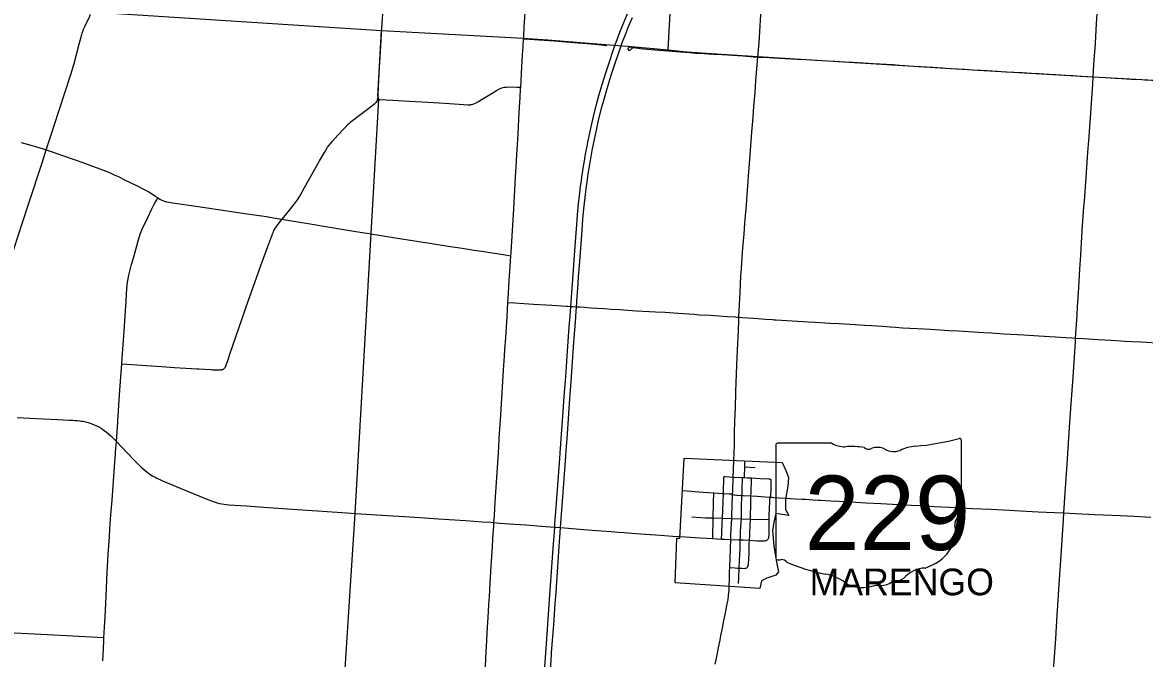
# Model space of a CAD drawing. Extents: x 1815539 to 1947826, y 273303 to 993194.
# Drawn here: x 1868609 to 1889640, y 872057 to 883973 of the extents above; entities that cross this region are included whole.
import ezdxf

# ---------------------------------------------------------------- set-up
doc = ezdxf.new("R2010")
doc.units = 0
for name, color, linetype in [('GM_X_City_Street', 7, 'Continuous'), ('GM_X_Corporation', 7, 'Continuous'), ('GM_X_Corporation_Text', 7, 'Continuous'), ('GM_X_County_Road', 7, 'Continuous'), ('GM_X_Interstate_Route', 7, 'Continuous'), ('GM_X_State_Route', 7, 'Continuous'), ('GM_X_Township', 7, 'Continuous'), ('GM_X_Township_Road', 7, 'Continuous'), ('SC_Shading3', 7, 'Continuous')]:
    doc.layers.add(name, color=color, linetype=linetype)

msp = doc.modelspace()

# ---------------------------------------------------------------- linework, layer by layer
at = {"layer": 'GM_X_City_Street'}
for points in [[(1881932, 875457), (1881937, 875598), (1881944, 875773)], [(1882141, 875447), (1882142, 875472), (1882148, 875648)], [(1882148, 875648), (1882150, 875743)], [(1882148, 875648), (1882345, 875639)], [(1881746, 875151), (1881748, 875210), (1881753, 875413), (1881754, 875448), (1881755, 875454), (1881756, 875459)], [(1881756, 875459), (1881758, 875463), (1881761, 875464), (1881763, 875465), (1881769, 875466), (1881779, 875465), (1881860, 875461), (1881932, 875457)], [(1881919, 875132), (1881922, 875192), (1881932, 875457)], [(1881932, 875457), (1882107, 875449)], [(1882094, 875113), (1882096, 875155), (1882098, 875223), (1882107, 875449)], [(1882107, 875449), (1882141, 875447)], [(1882141, 875447), (1882192, 875445), (1882275, 875440)], [(1882263, 875103), (1882265, 875158), (1882275, 875432), (1882275, 875440)], [(1882275, 875440), (1882437, 875431), (1882599, 875422), (1882610, 875421), (1882619, 875420), (1882625, 875418), (1882630, 875415), (1882634, 875412)], [(1882626, 875081), (1882633, 875113), (1882635, 875129), (1882639, 875210), (1882643, 875341), (1882643, 875363), (1882641, 875387), (1882639, 875401), (1882637, 875407), (1882634, 875412)], [(1880983, 875205), (1881064, 875200), (1881147, 875193), (1881212, 875188), (1881288, 875183), (1881370, 875176), (1881566, 875163)], [(1881557, 874690), (1881560, 874969), (1881566, 875163)], [(1881566, 875163), (1881728, 875152), (1881746, 875151)], [(1881729, 874686), (1881734, 874837), (1881746, 875151)], [(1881746, 875151), (1881854, 875143), (1881884, 875141), (1881899, 875140), (1881914, 875136), (1881919, 875132)], [(1882084, 874674), (1882085, 874772), (1882089, 874927), (1882093, 875074), (1882094, 875113)], [(1882252, 874668), (1882255, 874793), (1882259, 874868), (1882261, 874951), (1882262, 875016), (1882263, 875097), (1882263, 875103)], [(1882606, 874659), (1882607, 874738), (1882615, 875000), (1882618, 875050), (1882621, 875066), (1882626, 875081)], [(1881153, 874710), (1881236, 874706), (1881417, 874696), (1881557, 874690)], [(1881548, 874306), (1881557, 874690)], [(1881557, 874690), (1881729, 874686)], [(1881712, 874296), (1881717, 874404), (1881723, 874587), (1881729, 874686)], [(1881729, 874686), (1881902, 874681)], [(1881902, 874681), (1882084, 874674)], [(1882063, 874280), (1882065, 874335), (1882068, 874388), (1882069, 874430), (1882075, 874528), (1882084, 874674)], [(1882084, 874674), (1882252, 874668)], [(1882233, 874273), (1882237, 874298), (1882239, 874323), (1882240, 874345), (1882244, 874418), (1882249, 874545), (1882252, 874658), (1882252, 874668)], [(1882252, 874668), (1882606, 874659)], [(1882571, 874282), (1882582, 874294), (1882590, 874307), (1882596, 874321), (1882599, 874337), (1882602, 874368), (1882605, 874577), (1882606, 874659)], [(1881866, 873762), (1881884, 874288)], [(1881884, 874288), (1882039, 874281), (1882063, 874280)], [(1882043, 873751), (1882048, 873890), (1882053, 874009), (1882058, 874124), (1882062, 874259), (1882063, 874280)], [(1882063, 874280), (1882121, 874278), (1882233, 874273)], [(1882233, 874273), (1882235, 874272), (1882377, 874265), (1882453, 874263), (1882485, 874262), (1882517, 874264), (1882533, 874266), (1882549, 874271), (1882571, 874282)], [(1882186, 873759), (1882198, 873770), (1882206, 873781), (1882212, 873800), (1882216, 873816), (1882220, 873849), (1882222, 873898), (1882227, 874054), (1882229, 874164), (1882230, 874211), (1882233, 874263), (1882233, 874273)], [(1881855, 873411), (1881859, 873535), (1881863, 873690), (1881866, 873762)], [(1881866, 873762), (1881873, 873762), (1881959, 873756), (1882007, 873753), (1882043, 873751)], [(1882031, 873462), (1882034, 873561), (1882043, 873751)], [(1882043, 873751), (1882092, 873748), (1882137, 873747), (1882153, 873748), (1882170, 873753), (1882186, 873759)]]:
    msp.add_lwpolyline(points, dxfattribs=at)
at = {"layer": 'GM_X_Corporation'}
msp.add_lwpolyline([(1881014, 875812), (1882849, 875731), (1882917, 875580), (1882968, 875451), (1882954, 875285), (1882910, 875039), (1882912, 874849), (1882974, 874736), (1882727, 874773), (1882689, 874613), (1882670, 874451), (1882695, 874167), (1882739, 873862), (1882781, 873681), (1882728, 873621), (1882559, 873563), (1882458, 873515), (1882428, 873371), (1880842, 873478), (1880871, 874310), (1880929, 874307)], close=True, dxfattribs=at)
at = {"layer": 'GM_X_County_Road'}
for points in [[(1875340, 883767), (1875347, 883875), (1875368, 884219), (1875408, 884824), (1875439, 885315), (1875466, 885691), (1875483, 885919), (1875493, 886066), (1875504, 886222), (1875516, 886361), (1875526, 886521)], [(1882394, 883327), (1882396, 883347), (1882399, 883397), (1882414, 883594), (1882429, 883806), (1882450, 884118), (1882466, 884380), (1882480, 884592), (1882489, 884773), (1882494, 884904), (1882502, 885051), (1882505, 885117), (1882513, 885297), (1882517, 885379), (1882523, 885510), (1882528, 885641), (1882535, 885805), (1882538, 885887), (1882542, 885985), (1882549, 886108)], [(1888677, 882955), (1888685, 883069), (1888692, 883183), (1888703, 883347), (1888718, 883576), (1888726, 883707), (1888734, 883838), (1888745, 884050), (1888750, 884132), (1888766, 884378), (1888781, 884607), (1888793, 884803), (1888810, 885032), (1888820, 885196), (1888836, 885408), (1888848, 885605), (1888852, 885654)], [(1869055, 881586), (1869128, 881814), (1869298, 882328), (1869410, 882671), (1869517, 882998), (1869576, 883203), (1869673, 883568), (1869707, 883702), (1869716, 883732), (1869720, 883746), (1869727, 883770), (1869734, 883791), (1869744, 883819), (1869756, 883848), (1869765, 883870), (1869778, 883895), (1869843, 884028), (1869863, 884071), (1869881, 884118), (1869883, 884123)], [(1875266, 882530), (1875266, 882534), (1875270, 882552), (1875273, 882582), (1875284, 882778), (1875304, 883138), (1875332, 883629), (1875340, 883767)], [(1882038, 878451), (1882059, 878916), (1882067, 879063), (1882075, 879227), (1882079, 879292), (1882092, 879456), (1882100, 879570), (1882113, 879750), (1882133, 880012), (1882147, 880208), (1882159, 880355), (1882177, 880550), (1882193, 880747), (1882211, 880992), (1882219, 881106), (1882242, 881401), (1882275, 881842), (1882302, 882202), (1882319, 882398), (1882339, 882659), (1882357, 882888), (1882375, 883100), (1882394, 883327)], [(1888348, 878062), (1888353, 878138), (1888376, 878498), (1888385, 878646), (1888407, 879006), (1888429, 879349), (1888446, 879611), (1888466, 879955), (1888479, 880167), (1888504, 880511), (1888512, 880625), (1888551, 881165), (1888578, 881541), (1888593, 881754), (1888619, 882097), (1888670, 882817), (1888677, 882955)], [(1873476, 880289), (1873563, 880397), (1873708, 880574), (1873766, 880653), (1873810, 880722), (1873897, 880880), (1874034, 881123), (1874179, 881380), (1874268, 881537), (1874293, 881579), (1874329, 881637), (1874358, 881675), (1874420, 881751), (1874520, 881860), (1874642, 881992), (1874723, 882074), (1874772, 882118), (1874795, 882136), (1874902, 882219), (1875099, 882366), (1875189, 882435), (1875213, 882453), (1875226, 882465), (1875239, 882478), (1875244, 882483), (1875248, 882489), (1875253, 882497), (1875256, 882503), (1875261, 882512), (1875264, 882521), (1875266, 882530)], [(1866649, 876676), (1866673, 876713), (1866803, 876919), (1867040, 877293), (1867199, 877542), (1867365, 877805), (1867523, 878055), (1867681, 878305), (1867786, 878471), (1867936, 878706), (1868077, 878927), (1868253, 879204), (1868289, 879272), (1868302, 879298), (1868309, 879316), (1868322, 879354), (1868390, 879553), (1868526, 879975), (1868609, 880223), (1868720, 880567), (1868977, 881346), (1869055, 881586)], [(1871921, 877483), (1872131, 877470), (1872174, 877468), (1872233, 877465), (1872280, 877463), (1872303, 877463), (1872317, 877465), (1872335, 877467), (1872349, 877470), (1872357, 877473), (1872363, 877475), (1872375, 877480), (1872384, 877485), (1872391, 877491), (1872397, 877496), (1872402, 877501), (1872407, 877507), (1872411, 877513), (1872416, 877522), (1872420, 877529), (1872423, 877538), (1872454, 877624), (1872504, 877780), (1872664, 878246), (1872847, 878772), (1872995, 879190), (1873079, 879421), (1873208, 879775), (1873280, 879976), (1873299, 880025), (1873312, 880052), (1873322, 880073), (1873335, 880096), (1873346, 880114), (1873371, 880151), (1873460, 880269), (1873476, 880289)], [(1881944, 875773), (1881952, 876049), (1881957, 876279), (1881964, 876508), (1881971, 876754), (1881981, 877049), (1881987, 877229), (1881993, 877376), (1881999, 877557), (1882012, 877835), (1882028, 878195), (1882036, 878408), (1882038, 878451)], [(1888128, 874784), (1888154, 875161), (1888190, 875701), (1888216, 876094), (1888235, 876388), (1888258, 876748), (1888294, 877238), (1888331, 877795), (1888344, 877991), (1888348, 878062)], [(1870394, 876484), (1870396, 876514), (1870437, 877087), (1870460, 877414), (1870472, 877577)], [(1870472, 877577), (1871214, 877526), (1871460, 877510), (1871886, 877485), (1871921, 877483)], [(1870371, 876121), (1870394, 876484)], [(1870356, 875926), (1870371, 876121)], [(1870137, 872450), (1870143, 872537), (1870149, 872651), (1870154, 872733), (1870164, 872962), (1870176, 873224), (1870197, 873667), (1870218, 874011), (1870238, 874338), (1870248, 874486), (1870268, 874747), (1870291, 875025), (1870337, 875647), (1870354, 875892), (1870356, 875926)], [(1887918, 871548), (1887924, 871662), (1887953, 872087), (1887976, 872429), (1887990, 872658), (1888004, 872870), (1888017, 873050), (1888042, 873443), (1888071, 873901), (1888119, 874654), (1888128, 874784)], [(1881591, 871952), (1881615, 872067), (1881668, 872319), (1881683, 872399), (1881701, 872487), (1881717, 872568), (1881734, 872660), (1881750, 872737), (1881780, 872881), (1881800, 872979), (1881819, 873079), (1881833, 873160), (1881843, 873242), (1881852, 873340), (1881855, 873411)], [(1870115, 872014), (1870126, 872244), (1870134, 872391), (1870137, 872450)]]:
    msp.add_lwpolyline(points, dxfattribs=at)
at = {"layer": 'GM_X_Interstate_Route'}
for points in [[(1878372, 871564), (1878428, 872333), (1878482, 873069), (1878552, 874035), (1878585, 874519), (1878590, 874591), (1878613, 874886), (1878650, 875393), (1878674, 875720), (1878695, 875998), (1878743, 876686), (1878764, 876964), (1878785, 877258), (1878803, 877520), (1878812, 877635), (1878825, 877815), (1878858, 878273), (1878872, 878469), (1878886, 878654), (1878892, 878731), (1878899, 878829), (1878923, 879156), (1878956, 879615), (1878979, 879942), (1878997, 880187), (1879012, 880367), (1879024, 880498), (1879032, 880579), (1879048, 880726), (1879062, 880840), (1879071, 880905), (1879084, 881002), (1879096, 881083), (1879106, 881148), (1879121, 881246), (1879137, 881343), (1879151, 881423), (1879165, 881504), (1879183, 881601), (1879198, 881682), (1879207, 881730), (1879230, 881842), (1879268, 882019), (1879313, 882210), (1879365, 882417), (1879421, 882623), (1879476, 882812), (1879543, 883031), (1879604, 883218), (1879688, 883467), (1879708, 883521), (1879755, 883652), (1879808, 883790), (1879882, 883972), (1879977, 884199)], [(1879025, 879077), (1879033, 879208), (1879048, 879421), (1879074, 879748), (1879098, 880075), (1879114, 880288), (1879132, 880484), (1879154, 880696), (1879174, 880859), (1879192, 880989), (1879213, 881135), (1879242, 881314), (1879287, 881572), (1879328, 881782), (1879366, 881958), (1879414, 882166), (1879470, 882389), (1879522, 882579), (1879585, 882799), (1879643, 882988), (1879709, 883191), (1879784, 883408), (1879823, 883517), (1879845, 883578), (1879909, 883746), (1879971, 883899), (1880040, 884065)], [(1878974, 878366), (1878980, 878456), (1878989, 878571), (1878993, 878636), (1878994, 878648), (1878995, 878653), (1879000, 878718), (1879002, 878750), (1879020, 878996), (1879025, 879077)], [(1878830, 876359), (1878863, 876837), (1878881, 877082), (1878893, 877246), (1878907, 877426), (1878914, 877524), (1878946, 877982), (1878974, 878366)], [(1878793, 875843), (1878801, 875953), (1878818, 876182), (1878830, 876359)], [(1878598, 873152), (1878604, 873221), (1878610, 873303), (1878643, 873777), (1878677, 874252), (1878689, 874415), (1878696, 874510), (1878738, 875086), (1878768, 875511), (1878793, 875843)], [(1878526, 872162), (1878566, 872697), (1878593, 873090), (1878598, 873152)], [(1878393, 870309), (1878407, 870521), (1878419, 870685), (1878440, 870963), (1878463, 871290), (1878503, 871830), (1878525, 872141), (1878526, 872162)]]:
    msp.add_lwpolyline(points, dxfattribs=at)
at = {"layer": 'GM_X_State_Route'}
for points in [[(1877447, 874606), (1877455, 874740), (1877471, 874986), (1877494, 875362), (1877518, 875722), (1877537, 876017), (1877547, 876181), (1877573, 876623), (1877594, 876933), (1877615, 877244), (1877628, 877457), (1877644, 877719), (1877652, 877850), (1877666, 878063), (1877691, 878456), (1877708, 878729), (1877719, 878897), (1877733, 879143), (1877743, 879307), (1877756, 879503), (1877763, 879600), (1877767, 879667), (1877786, 879978), (1877810, 880371), (1877837, 880829), (1877851, 881075), (1877861, 881271), (1877875, 881500), (1877892, 881779), (1877905, 882008), (1877914, 882172), (1877926, 882384), (1877936, 882565), (1877946, 882728), (1877948, 882762), (1877955, 882875), (1877963, 883023), (1877969, 883137), (1877983, 883366), (1877991, 883514), (1878002, 883665), (1878004, 883711), (1878014, 883891), (1878029, 884153)], [(1868509, 876574), (1868869, 876554), (1869263, 876537), (1869379, 876530), (1869479, 876525)], [(1869479, 876525), (1869494, 876524), (1869554, 876521), (1869592, 876518), (1869632, 876515), (1869677, 876510), (1869710, 876506), (1869740, 876501), (1869774, 876495), (1869814, 876486), (1869841, 876479), (1869876, 876468), (1869909, 876455), (1869952, 876438), (1869985, 876424), (1870026, 876403), (1870082, 876371), (1870138, 876332), (1870183, 876298), (1870223, 876264), (1870270, 876221), (1870344, 876149), (1870371, 876121), (1870695, 875781), (1870834, 875642), (1870908, 875577), (1870947, 875546), (1870974, 875527), (1871014, 875500), (1871043, 875483), (1871094, 875454), (1871130, 875435), (1871207, 875399)], [(1871207, 875399), (1871234, 875386), (1871567, 875248), (1871916, 875103), (1872113, 875023), (1872222, 874985), (1872258, 874974), (1872301, 874963), (1872346, 874954), (1872425, 874943), (1872480, 874936), (1872808, 874915), (1873135, 874891), (1873577, 874861), (1873953, 874837), (1874510, 874799), (1874769, 874782), (1874952, 874770), (1875443, 874739), (1875770, 874715), (1876146, 874690), (1876408, 874673), (1876916, 874641), (1877227, 874619), (1877391, 874609), (1877447, 874606)], [(1881889, 874394), (1881902, 874681), (1881904, 874741), (1881910, 874906), (1881919, 875132)], [(1881919, 875132), (1881941, 875125), (1881950, 875122), (1881962, 875121), (1881999, 875119), (1882094, 875113), (1882118, 875111), (1882263, 875103), (1882380, 875096), (1882531, 875088), (1882626, 875081), (1882661, 875080), (1882694, 875077)], [(1882694, 875077), (1882795, 875070), (1882918, 875062)], [(1882918, 875062), (1883090, 875051), (1883219, 875044)], [(1883219, 875044), (1883285, 875040), (1883420, 875031), (1883530, 875026)], [(1883530, 875026), (1883559, 875024), (1883761, 875013), (1883908, 875005), (1884138, 874993), (1884416, 874977), (1884695, 874960), (1885137, 874936), (1885268, 874930), (1885448, 874921), (1885694, 874908), (1885989, 874893), (1886202, 874883), (1886415, 874871), (1886759, 874853), (1887103, 874835), (1887316, 874825), (1887644, 874807), (1887955, 874792), (1888128, 874784), (1888349, 874773), (1888709, 874757), (1889184, 874737), (1889446, 874722), (1889758, 874704)], [(1877285, 871892), (1877296, 872072), (1877308, 872285), (1877328, 872645), (1877338, 872825), (1877351, 873071), (1877361, 873218), (1877376, 873464), (1877394, 873791), (1877404, 873971), (1877416, 874151), (1877425, 874299), (1877443, 874544), (1877447, 874606)], [(1877447, 874606), (1877555, 874595), (1877735, 874583), (1878044, 874559), (1878338, 874538), (1878583, 874519), (1878585, 874519), (1878696, 874510), (1878844, 874499), (1879056, 874482), (1879284, 874465), (1879464, 874451), (1879643, 874437), (1879782, 874426)], [(1879782, 874426), (1879888, 874418), (1880100, 874402), (1880566, 874369)], [(1880566, 874369), (1880876, 874346), (1880935, 874342)], [(1880935, 874342), (1881310, 874320), (1881548, 874306), (1881712, 874296), (1881766, 874293), (1881884, 874288), (1881884, 874291), (1881889, 874394)]]:
    msp.add_lwpolyline(points, dxfattribs=at)
at = {"layer": 'GM_X_Township'}
for points in [[(1880714, 883463), (1880836, 885744), (1880863, 886256), (1881338, 891636), (1881703, 897023), (1881803, 900282), (1881806, 900375), (1881918, 903829), (1881985, 905459), (1882074, 908232), (1882082, 908847), (1882260, 912507), (1887758, 913255), (1888309, 913332)], [(1850147, 879854), (1850364, 882693), (1850523, 884772), (1850567, 885340), (1853740, 885139), (1854805, 885081), (1854864, 885092), (1854977, 885091), (1857606, 884909), (1869894, 884174), (1875339, 883824)], [(1873671, 857558), (1873806, 859043), (1874029, 862389), (1874586, 870801), (1874844, 874776), (1875147, 880018), (1875287, 882532), (1875268, 882593), (1875339, 883824), (1877996, 883681), (1878453, 883649), (1879771, 883544), (1879947, 883530), (1880714, 883463), (1881064, 883424), (1881619, 883383), (1882389, 883337), (1886519, 883080), (1888679, 882953), (1894036, 882664)]]:
    msp.add_lwpolyline(points, dxfattribs=at)
at = {"layer": 'GM_X_Township_Road'}
for points in [[(1878002, 883665), (1878106, 883658), (1878204, 883653), (1878286, 883647), (1878580, 883626), (1878727, 883615), (1878874, 883604), (1879022, 883592), (1879267, 883571), (1879462, 883552), (1879544, 883542), (1879560, 883541)], [(1880034, 883504), (1880028, 883507), (1880019, 883510), (1880011, 883512), (1880003, 883513), (1879995, 883513), (1879987, 883512), (1879979, 883509), (1879975, 883507), (1879971, 883505), (1879965, 883500), (1879961, 883493), (1879958, 883486), (1879956, 883477), (1879957, 883474), (1879957, 883470), (1879959, 883466), (1879962, 883460), (1879965, 883458), (1879970, 883455), (1879975, 883453), (1879981, 883452), (1879987, 883452), (1879993, 883454), (1879999, 883457), (1880006, 883461), (1880018, 883471), (1880041, 883496), (1880045, 883498), (1880050, 883501), (1880055, 883502), (1880060, 883502), (1880071, 883502), (1880185, 883486), (1880251, 883480), (1880463, 883461), (1880627, 883448), (1880715, 883441)], [(1880715, 883441), (1880856, 883429), (1881118, 883410), (1881232, 883401), (1881297, 883397), (1881559, 883380), (1881723, 883370), (1881919, 883358), (1882116, 883345), (1882312, 883332), (1882394, 883327)], [(1882394, 883327), (1882410, 883326), (1882607, 883314), (1882689, 883309), (1882901, 883298), (1883131, 883286), (1883294, 883278), (1883475, 883268), (1883589, 883262), (1883704, 883254), (1883835, 883247), (1884019, 883237), (1884179, 883228), (1884277, 883221), (1884368, 883217), (1884462, 883211), (1884555, 883206), (1884686, 883199), (1884801, 883192), (1884931, 883183), (1885046, 883175), (1885144, 883168), (1885308, 883156), (1885439, 883148), (1885668, 883133), (1885853, 883122), (1886007, 883113), (1886266, 883098), (1886420, 883088), (1886567, 883081), (1886698, 883072), (1886878, 883059), (1887042, 883049), (1887190, 883043), (1887353, 883033), (1887517, 883024), (1887664, 883014), (1887845, 883004), (1887976, 882996), (1888156, 882985), (1888303, 882977), (1888434, 882969), (1888677, 882955)], [(1888677, 882955), (1888900, 882943), (1889097, 882929), (1889212, 882923), (1889392, 882913), (1889589, 882902), (1889638, 882899), (1889900, 882886)], [(1875266, 882530), (1875306, 882528), (1875421, 882525), (1875552, 882518), (1875748, 882505), (1876206, 882479), (1876517, 882462), (1876795, 882444), (1876959, 882433), (1876992, 882433), (1877008, 882434), (1877024, 882436), (1877040, 882439), (1877072, 882448), (1877102, 882461), (1877145, 882484), (1877257, 882552), (1877411, 882647), (1877496, 882696), (1877553, 882728), (1877583, 882741), (1877614, 882752), (1877646, 882760), (1877678, 882764), (1877727, 882765), (1877875, 882762), (1877924, 882762), (1877948, 882762)], [(1868582, 881726), (1868724, 881687), (1868976, 881612), (1869055, 881586)], [(1869055, 881586), (1869163, 881552), (1869379, 881475), (1869580, 881404), (1869719, 881354), (1869872, 881298), (1870057, 881229), (1870242, 881160), (1870263, 881150), (1870331, 881119), (1870421, 881079), (1870523, 881027), (1870744, 880920), (1870890, 880847), (1870977, 880801), (1871046, 880756), (1871111, 880712), (1871148, 880687)], [(1870472, 877577), (1870484, 877773), (1870508, 878099), (1870539, 878573), (1870551, 878752), (1870566, 878996), (1870579, 879109), (1870589, 879173), (1870602, 879237), (1870656, 879442), (1870694, 879585), (1870750, 879790), (1870777, 879884), (1870823, 880023), (1870854, 880099), (1870951, 880304), (1871035, 880481), (1871079, 880568), (1871103, 880611), (1871128, 880653), (1871148, 880687)], [(1871148, 880687), (1871197, 880658), (1871219, 880647), (1871241, 880637), (1871266, 880628), (1871283, 880621), (1871297, 880617), (1871307, 880615), (1871351, 880607), (1871386, 880601), (1871903, 880526), (1872195, 880483), (1872779, 880395), (1872957, 880370), (1873184, 880336), (1873346, 880309), (1873476, 880289)], [(1873476, 880289), (1873540, 880278), (1873961, 880210), (1874333, 880147), (1874819, 880066), (1875101, 880019)], [(1875101, 880019), (1875637, 879932), (1876284, 879831), (1876591, 879783), (1876850, 879743), (1877076, 879709), (1877222, 879686), (1877659, 879618), (1877723, 879607), (1877763, 879600)], [(1877708, 878729), (1877716, 878729), (1877839, 878720), (1878005, 878708), (1878185, 878698), (1878529, 878677), (1878807, 878659), (1878830, 878658)], [(1878830, 878658), (1878886, 878654), (1878922, 878652), (1878994, 878648), (1879053, 878644), (1879146, 878637)], [(1879146, 878637), (1879265, 878628), (1879511, 878612), (1879642, 878604), (1879805, 878594), (1879953, 878584), (1880116, 878574), (1880477, 878554), (1880657, 878543), (1880898, 878527), (1881200, 878506), (1881299, 878499), (1881507, 878487), (1881818, 878467), (1881965, 878456), (1882014, 878452), (1882030, 878451), (1882038, 878451)], [(1882038, 878451), (1882096, 878449), (1882309, 878433), (1882390, 878428), (1882537, 878417), (1882668, 878408), (1882700, 878405), (1882733, 878403)], [(1882733, 878403), (1883334, 878366), (1883465, 878359), (1883744, 878343), (1883908, 878335), (1884124, 878321), (1884399, 878302), (1884527, 878294), (1884729, 878281), (1884874, 878270), (1884972, 878264), (1885103, 878255), (1885381, 878239), (1885627, 878225), (1885807, 878215), (1885971, 878204), (1886151, 878194), (1886249, 878189), (1886627, 878166), (1886773, 878156), (1887002, 878142), (1887379, 878120), (1887657, 878103), (1887969, 878086), (1888165, 878074), (1888280, 878067), (1888348, 878062)], [(1888348, 878062), (1888493, 878053), (1888771, 878035), (1889017, 878020), (1889279, 878004), (1889393, 877997), (1889574, 877988), (1889972, 877965)], [(1865034, 872721), (1865039, 872722), (1865048, 872723), (1865057, 872724), (1865063, 872724), (1865074, 872724), (1865121, 872723), (1865174, 872719), (1865240, 872715), (1865615, 872691), (1866008, 872671), (1866318, 872656), (1866625, 872639), (1866969, 872621), (1867244, 872605), (1867583, 872585), (1867992, 872562), (1868336, 872544), (1868958, 872513), (1869318, 872493), (1870137, 872450)]]:
    msp.add_lwpolyline(points, dxfattribs=at)
at = {"layer": 'SC_Shading3'}
for p, q in [((1882728, 876055), (1882728, 873942)), ((1883781, 876092), (1882762, 876092)), ((1886208, 875039), (1886208, 876144)), ((1886208, 875039), (1886208, 875039))]:
    msp.add_line(p, q, dxfattribs=at)
for centre, major_axis, start_param, end_param in [((1884968, 878973), (3691, 0), 4.814394, 5.042369), ((1886169, 876149), (38.7, 0), 6.141152, 7.989035), ((1882767, 876060), (40.3, 0), 1.712693, 3.28349), ((1884024, 876337), (391, 0), 4.042523, 4.731795), ((1884153, 874905), (1404, 0), 1.404758, 1.657858), ((1884472, 876071), (113, 0), 3.836095, 5.185415), ((1884638, 875826), (235, 0), 0.950623, 2.079405), ((1884941, 876161), (282, 0), 4.081561, 5.145723), ((1885439, 875446), (743, 0), 1.699011, 2.107814), ((1886199, 874957), (60, 0), 1.883978, 3.671073), ((1885818, 874818), (360, 0), 5.934695, 6.695948), ((1886167, 875034), (41.5, 0), 5.05454, 6.418171), ((1886347, 874576), (262, 0), 2.387724, 3.262537), ((1885175, 874435), (923, 0), 5.101752, 6.440018), ((1882768, 873937), (40.7, 0), 3.00124, 4.508301), ((1882774, 874154), (310, 0), 4.665946, 4.897461), ((1882837, 873820), (112, 0), 0.519207, 1.627899), ((1884251, 875719), (2665, 0), 4.195997, 4.488961), ((1885564, 873349), (506, 0), 1.647645, 2.488434), ((1883456, 872993), (834, 0), 0.823519, 1.323587), ((1884358, 873810), (529, 0), 4.026481, 4.996735), ((1884702, 873651), (282, 0), 4.691044, 5.507374), ((1884957, 873447), (79.4, 0), 1.147584, 2.315152), ((1884924, 873737), (298, 0), 4.937069, 5.64225), ((1884664, 873079), (435, 0), 1.495662, 1.94098)]:
    msp.add_ellipse(centre, major_axis=major_axis, ratio=0.8, start_param=start_param, end_param=end_param, dxfattribs=at)

# ---------------------------------------------------------------- texts
at = {"layer": 'GM_X_Corporation_Text'}
msp.add_text('MARENGO', height=500, rotation=0, dxfattribs=at).set_placement((1883362, 873242))
at = {"layer": 'SC_Shading3'}
msp.add_text('229', height=1392.2, dxfattribs=at).set_placement((1883267, 874091))

doc.saveas('drawing.dxf')
